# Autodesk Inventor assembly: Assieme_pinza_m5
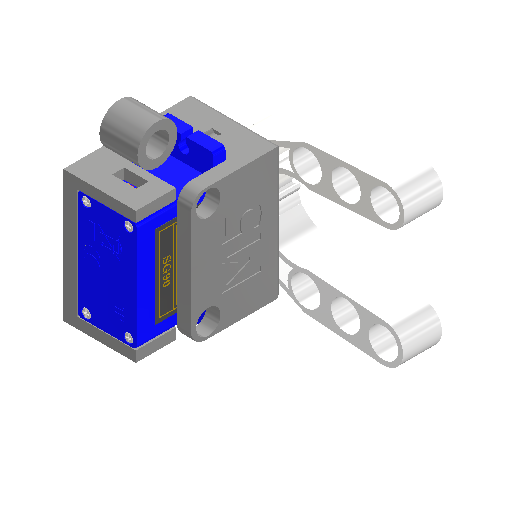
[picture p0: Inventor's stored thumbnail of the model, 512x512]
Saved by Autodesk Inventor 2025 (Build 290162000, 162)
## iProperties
Created: 2021-06
Part Number: Assieme_pinza_m5
Document SubType Name: Assembly
Designer: Ryzen5700u
Author: Ryzen5700u
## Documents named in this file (6)
- C:\Users\Ryzen5700u\Desktop\m5\Assieme_2_robot\Assieme_pinza_m5.iam
- C:\Users\Ryzen5700u\Desktop\m5\Assieme_2_robot\Ingranaggio cilindrico11_MIR.ipt
- C:\Users\Ryzen5700u\Desktop\m5\Assieme_2_robot\Ingranaggio cilindrico11.ipt
- C:\Users\Ryzen5700u\Desktop\m5\Assieme_2_robot\SG90 - Micro Servo 9g - Tower Pro.1_Pea.ipt
- C:\Users\Ryzen5700u\Desktop\m5\Assieme_2_robot\corpo_m5.ipt
- C:\Users\Ryzen5700u\Desktop\m5\Assieme_2_robot\AS 1420 - 1973 - M3 x 6.ipt
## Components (5 placed, 5 different names)
1. Ingranaggio cilindrico11_MIR:1
2. Ingranaggio cilindrico1:1
3. SG90 - Micro Servo 9g - Tower Pro.1_Pea:1
4. corpo_m5:1
5. AS 1420 - Metrico M3 x 6:1
